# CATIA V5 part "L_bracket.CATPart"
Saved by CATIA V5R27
Part number: L_bracket
Revision: ANY
Definition: UNKNOWN
Nomenclature: L_bracket
Source: Unknown
Bounding box of the stored display mesh (mm): x 0 to 76.2, y 0 to 76.2, z -16.637 to 16.637
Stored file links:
  \\triton.meca.polymtl.ca\usagers\zaoue\profiles\Desktop\varm_ass\structure prismatique\L_bracket.CATPart
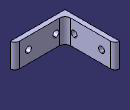
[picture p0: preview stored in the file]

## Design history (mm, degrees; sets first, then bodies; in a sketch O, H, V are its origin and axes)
Body1 "Cut-Extrude2" (main body)
  Solid1: solid without history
